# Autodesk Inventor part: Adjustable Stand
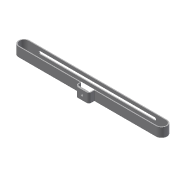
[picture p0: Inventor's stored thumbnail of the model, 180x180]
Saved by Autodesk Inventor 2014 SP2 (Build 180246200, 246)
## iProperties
Created: 2015-04
Part Number: Adjustable Stand
Material: Steel
Document SubType Name: Modeling
Designer: SFC
Density: 7.85 g/cm^3
Appearance: Steel
Author: SFC
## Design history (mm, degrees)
sketch "Sketch1"
  geometry: L1 (-10.5, 0)-(10.5, 0); L2 (13.5, 3)-(13.5, 9.1); L3 (16.5, 12.1)-(150, 12.1); L4 (150, 32.1)-(-150, 32.1); L5 (-150, 12.1)-(-16.5, 12.1); L6 (-13.5, 9.1)-(-13.5, 5.1); L7 (-10.5, 2.1)-(10.5, 2.1); L8 (-15.5, 5.1)-(-15.5, 9.1); L9 (-16.5, 10.1)-(-150, 10.1); L10 (-150, 34.1)-(150, 34.1); L11 (150, 10.1)-(16.5, 10.1); L12 (15.5, 9.1)-(15.5, 3); L13 (10.5, -2)-(-10.5, -2); L14 (10.5, 2.1)-(10.5, 0.1); L15 (-10.5, -2)-(-10.5, 0); L16 (-10.5, 0.1)-(10.5, 0.1); A1 r 10 centre (150, 22.1) between (150, 12.1) and (150, 32.1); A2 r 10 centre (-150, 22.1) between (-150, 32.1) and (-150, 12.1); A3 r 3 centre (-16.5, 9.1) between (-13.5, 9.1) and (-16.5, 12.1); A4 r 3 centre (-10.5, 5.1) between (-13.5, 5.1) and (-10.5, 2.1); A5 r 3 centre (10.5, 3) between (10.5, 0) and (13.5, 3); A6 r 3 centre (16.5, 9.1) between (16.5, 12.1) and (13.5, 9.1); A7 r 5 centre (-10.5, 5.1) between (-15.5, 5.1) and (-10.5, 0.1); A8 r 1 centre (-16.5, 9.1) between (-15.5, 9.1) and (-16.5, 10.1); A9 r 12 centre (-150, 22.1) between (-150, 34.1) and (-150, 10.1); A10 r 12 centre (150, 22.1) between (150, 10.1) and (150, 34.1); A11 r 1 centre (16.5, 9.1) between (16.5, 10.1) and (15.5, 9.1); A12 r 5 centre (10.5, 3) between (10.5, -2) and (15.5, 3); 6 further points
  constraints: 32 end point, 24 point on circle, 13 tangent, 12 centre point, 11 parallel, 4 point on line, 3 equal radius, 3 midpoint, 3 perpendicular, 2 collinear, 2 vertical alignment, 1 coincident, 1 horizontal, 11 other
  dimensions: "d0" = 24 distance of L1.start point (13.5, 0); "d1" = 24 distance of point (-13.5, 2.1) L7.end (= d0); "d3" = 2.1 distance between parallel lines of L1 L7; "d4" = 10 distance between parallel lines of L5 L7; "d5" = 10 radius of A1; "d6" = 300 distance of L4.start L4.end; "d7" = 3 radius of A3; "d8" = 2 distance between parallel lines of L3 L11
extrude "Extrusion1" new body sketch "Sketch1" distance "d9" = 20; taper "d10" = 0 deg
sketch "Sketch2"
  geometry: L1 (0, 0)-(21, 20); 2 further points
  constraints: 2 end point, 1 midpoint
hole "Hole1" sketch "Sketch2" at (10.5, 10) diameter "d11" = 6; stored, may be unused: countersink angle "d15" = 90 deg, drill point angle "d17" = 118 deg; dims "d12" = 6, "d13" = 4, "d14" = 2, "d16" = 8
sketch "Sketch3"
  geometry: L1 (0, 0)-(300, 0) reference; L2 (0, 0)-(0, -20) reference; L3 (25, -10)-(275, -10); L4 (25, -13)-(275, -13); L5 (275, -7)-(25, -7); A1 r 3 centre (25, -10) between (25, -7) and (25, -13); A2 r 3 centre (275, -10) between (275, -13) and (275, -7); 4 further points
  constraints: 8 end point, 4 point on circle, 4 tangent, 3 midpoint, 2 centre point, 2 parallel, 1 point on line, 1 vertical alignment
  dimensions: "d18" = 6 diameter of A2; "d19" = 250 distance of L4.start L4.end
extrude "Extrusion2" cut sketch "Sketch3" stored distance "d21" = 20; taper "d22" = 0 deg
body "Solid1"
